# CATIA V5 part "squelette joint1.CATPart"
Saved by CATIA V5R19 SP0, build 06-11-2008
Part number: squelette joint1
Publications: "Plan.1", "Plan.2", "Point.1", "Droite.1", "Point.2", "Droite.2", "Droite.3", "entraxe", "longeur du joint", "epaisseur", "hauteur", "distance entre trou et bord"
Bounding box of the stored display mesh (mm): x 0 to 50, y -40 to 0, z 0 to 0
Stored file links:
  I:\yyang\yyang\squelette joint1.CATPart
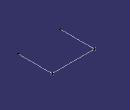
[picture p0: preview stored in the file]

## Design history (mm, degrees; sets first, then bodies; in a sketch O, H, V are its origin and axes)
Parameters
  entraxe = 50 mm
  `longeur du joint` = 80 mm
  epaisseur = 3 mm
  hauteur = 25 mm
  `distance entre trou et bord` = 10 mm
Body1 (main body)
  Plane1: type Offset, Offset 0, RefPlane zx-plane
  Plane2: type Offset, Offset 0, RefPlane yz-plane
  Point1: (0, 0, 0)
  Point2: (50 {= entraxe}, 0, 0)
  Line1: type PtPt, SecondPoint Point2, FirstPoint Point1
  Line2: type PtDir, Direction (0, 1, 0), Start 0, End 40, RefPoint Point1
  Line3: type PtDir, Direction (0, 1, 0), Start 0, End 40, RefPoint Point2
